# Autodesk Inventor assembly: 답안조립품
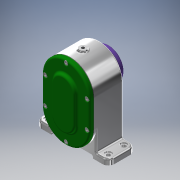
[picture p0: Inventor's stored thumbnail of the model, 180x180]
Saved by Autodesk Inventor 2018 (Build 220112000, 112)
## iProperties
Created: 2021-05
Part Number: 답안조립품
Material: 일반
Document SubType Name: Assembly
Designer: admin
Author: admin
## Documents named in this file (19)
- C:\Users\admin\Desktop\710509V1003\답안조립품.iam
- C:\Users\admin\Desktop\710509V1003\본체.ipt
- C:\Users\admin\Desktop\710509V1003\710509V1003\베어링 6001.ipt
- 베어링 6001.ipt
- C:\Users\admin\Desktop\710509V1003\710509V1003\축 A.ipt
- C:\Users\admin\Desktop\710509V1003\710509V1003\축 B.ipt
- C:\Users\admin\Desktop\710509V1003\710509V1003\칼라.ipt
- C:\Users\admin\Desktop\710509V1003\710509V1003\커버 B.ipt
- C:\Users\admin\Desktop\710509V1003\710509V1003\개스킷 B.ipt
- C:\Users\admin\Desktop\710509V1003\710509V1003\오일 실 12 22 7.ipt
- C:\Users\admin\Desktop\710509V1003\710509V1003\베어링 6002.ipt
- 베어링 6002.ipt
- C:\Users\admin\Desktop\710509V1003\710509V1003\개스킷 A.ipt
- C:\Users\admin\Desktop\710509V1003\710509V1003\커버 A.ipt
- C:\Users\admin\Desktop\710509V1003\710509V1003\키 5 x 5 x 12.ipt
- C:\Users\admin\Desktop\710509V1003\710509V1003\키 4 x 4 x 12.ipt
- C:\Users\admin\Desktop\710509V1003\710509V1003\스퍼기어 A.ipt
- C:\Users\admin\Desktop\710509V1003\710509V1003\스퍼기어 B.ipt
- C:\Users\admin\Desktop\710509V1003\710509V1003\볼트 M4.ipt
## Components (2 placed, 2 different names)
1. 개스킷 B:1
2. 개스킷 A:1
